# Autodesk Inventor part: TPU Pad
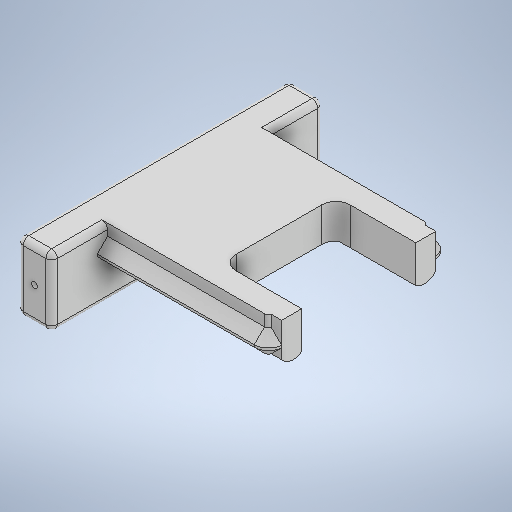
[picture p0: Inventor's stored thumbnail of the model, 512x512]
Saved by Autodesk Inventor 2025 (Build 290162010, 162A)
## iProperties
Created: 2023-12
Part Number: TPU Pad
Material: Generic
Document SubType Name: Modeling
Designer: Andrew
Density: 1 g/cm^3
Appearance: Default
Author: Andrew
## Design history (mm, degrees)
sketch "Sketch1"
  geometry: L1 (22.86, 20.066)-(-22.86, 20.066); L2 (-22.86, 20.066)-(-22.86, -20.066); L3 (-22.86, -20.066)-(22.86, -20.066); L4 (22.86, -20.066)-(22.86, 20.066); 2 further points
  constraints: 8 end point, 2 parallel, 1 horizontal, 1 midpoint, 1 perpendicular
  dimensions: "d0" = 45.72 distance between parallel lines of L2 L4; "d1" = 40.132 distance between parallel lines of L3 L1; "d2" = 22.86 distance of point (0, 0) point (22.86, 0) (= 0.5 x d0); "d3" = 20.066 distance from line of point (0, 0) L1 (= 0.5 x d1)
extrude "Extrusion1" new body sketch "Sketch1" distance "d4" = 5.08; taper "d5" = 0 deg
fillet "Fillet1" dims "d6" = 3.175
sketch "Sketch2"
  geometry: L1 (29.21, -12.7)-(5.08, -12.7); L2 (5.08, -12.7)-(5.08, 12.7); L3 (5.08, 12.7)-(29.21, 12.7); L4 (29.21, 12.7)-(29.21, -12.7); L5 (22.86, -16.891)-(22.86, 16.891) reference; 1 further point
  constraints: 8 end point, 2 parallel, 1 horizontal, 1 perpendicular
  dimensions: "d10" = 25.4 distance between parallel lines of L3 L1; "d11" = 12.7 distance from line of point (0, 0) L1 (= 0.5 x d10); "d19" = 17.78 distance between parallel lines of L5 L2
extrude "Extrusion2" cut sketch "Sketch2" extent not by distance; stored distance "d13" = 0; taper "d14" = 0 deg
fillet "Fillet2" dims "d15" = 3.175
chamfer "Chamfer2" distance "d16" = 2.286; stored, may be unused: second distance "d17" = 3.175, angle "d18" = 45 deg
sketch "Sketch3"
  geometry: L1 (-22.86, -16.891)-(-22.86, 16.891) reference; L2 (-22.86, 30.226)-(-15.24, 30.226); L3 (-15.24, 30.226)-(-15.24, -30.226); L4 (-15.24, -30.226)-(-22.86, -30.226); L5 (-22.86, -30.226)-(-22.86, 30.226); L6 (-19.685, -20.066)-(19.685, -20.066) reference; L7 (19.685, 20.066)-(-19.685, 20.066) reference; A1 r 3.175 centre (-19.685, 16.891) between (-19.685, 20.066) and (-22.86, 16.891) reference; A2 r 3.175 centre (-19.685, -16.891) between (-22.86, -16.891) and (-19.685, -20.066) reference; 10 further points
  constraints: 8 end point, 2 parallel, 1 horizontal, 1 perpendicular, 1 point on line
  dimensions: "d20" = 30.226 distance from line of point (0, 0) L2 (= 0.5 x d21); "d21" = 60.452 distance of L2.end L3.end (computed from d41); "d22" = 7.62 distance between parallel lines of L1 L3; "d41" = 40.132 distance between parallel lines of L6 L7 (derived)
extrude "Extrusion3" join sketch "Sketch3" distance "d23" = 7.62; taper "d25" = 0 deg; dims "d24" = 5.08, "d26" = 0
sketch "Sketch9"
  geometry: L1 (22.86, 17.145)-(-15.24, 17.145); L2 (-15.24, 17.145)-(-15.24, 12.065); L3 (-15.24, 12.065)-(22.86, 12.065); L4 (22.86, 12.065)-(22.86, 17.145); L5 (22.86, -17.145)-(-15.24, -17.145); L6 (-15.24, -17.145)-(-15.24, -12.065); L7 (-15.24, -12.065)-(22.86, -12.065); L8 (22.86, -12.065)-(22.86, -17.145); L9 (-15.24, -30.226)-(-15.24, 30.226) reference; L10 (5.08, -9.525)-(5.08, 9.525) reference; L11 (20.574, 16.891)-(20.574, 12.7) reference; L12 (22.86, 12.7)-(22.86, 16.891) reference; L13 (20.574, 12.7)-(22.86, 12.7) reference; L14 (8.255, 12.7)-(20.574, 12.7) reference; L15 (20.574, -12.7)-(8.255, -12.7) reference; L16 (22.86, -12.7)-(20.574, -12.7) reference; A1 r 3.175 centre (8.255, 9.525) between (8.255, 12.7) and (5.08, 9.525) reference; A2 r 3.175 centre (8.255, -9.525) between (5.08, -9.525) and (8.255, -12.7) reference; 10 further points
  constraints: 16 end point, 4 parallel, 2 horizontal, 2 midpoint, 2 perpendicular, 1 collinear
  dimensions: "d56" = 34.29 distance from line of L5 point (3.81, 17.145); "d57" = 5.08 distance between parallel lines of L3 L1; "d58" = 5.08 distance between parallel lines of L5 L7 (= d57); "d59" = 0 distance from line of L9 point (-15.24, 14.605); "d62" = 0 distance between parallel lines of L12 L4; "d67" = 0 distance between parallel lines of L9 L6; "d68" = 17.145 distance from line of point (0, 0) L1 (= 0.5 x d56)
extrude "Extrusion9" join sketch "Sketch9" distance "d69" = 3.81; taper "d71" = 0 deg; dims "d70" = 5.08, "d72" = 0
sketch "Sketch11"
  geometry: L1 (8.255, 12.7)-(22.86, 12.7) reference; L2 (22.86, 12.7)-(22.86, 17.145) reference; L3 (22.86, 17.145)-(20.537, 17.145) reference; L4 (-15.24, 17.78)-(19.685, 17.78) reference; L5 (-15.24, 17.78)-(-15.24, 30.226) reference; L6 (-15.24, 30.226)-(-22.86, 30.226) reference; L7 (-22.86, 30.226)-(-22.86, -30.226) reference; L8 (-22.86, -30.226)-(-15.24, -30.226) reference; L9 (-15.24, -30.226)-(-15.24, -17.78) reference; L10 (19.685, -17.78)-(-15.24, -17.78) reference; L11 (20.537, -17.145)-(22.86, -17.145) reference; L12 (22.86, -17.145)-(22.86, -12.7) reference; L13 (22.86, -12.7)-(8.255, -12.7) reference; L14 (5.08, -9.525)-(5.08, 9.525) reference; A1 r 3.175 centre (8.255, 9.525) between (8.255, 12.7) and (5.08, 9.525) reference; A2 r 0.889 centre (19.685, 16.891) between (20.537, 17.145) and (19.685, 17.78) reference; A3 r 0.889 centre (19.685, -16.891) between (19.685, -17.78) and (20.537, -17.145) reference; A4 r 3.175 centre (8.255, -9.525) between (5.08, -9.525) and (8.255, -12.7) reference; 1 further point
extrude "Extrusion10" join sketch "Sketch11" distance "d74" = 2.54; taper "d75" = 0 deg
fillet "Fillet3" dims "d33" = 1.27
sketch "Sketch7"
  geometry: L1 (-1.27, 12.7)-(-1.27, 0) reference; L2 (6.35, 0)-(6.35, 12.7) reference; L3 (0, -1.27)-(5.08, -1.27) reference; L4 (5.08, 13.97)-(0, 13.97) reference; C1 r 0.635 at (2.54, 6.35); 3 further points
  constraints: 1 centre point, 1 midpoint
  dimensions: "d49" = 1.27 diameter of C1; "d50" = 7.62 distance between parallel lines of L1 L2 (derived); "d52" = 7.62 distance from line of L3 C1.centre (= 0.5 x d77); "d53" = 3.81 distance from line of L2 C1.centre (= 0.5 x d50); "d77" = 15.24 distance between parallel lines of L3 L4 (derived)
extrude "Extrusion7" cut sketch "Sketch7" extent not by distance; stored distance "d54" = 0; taper "d55" = 0 deg
fillet "Fillet5" dims "d78" = 3.175
body "Solid1"
node "Projected Loop2"
other parameters: "d51" = 12.7 (derived), "d76" = 17.78 (derived)
